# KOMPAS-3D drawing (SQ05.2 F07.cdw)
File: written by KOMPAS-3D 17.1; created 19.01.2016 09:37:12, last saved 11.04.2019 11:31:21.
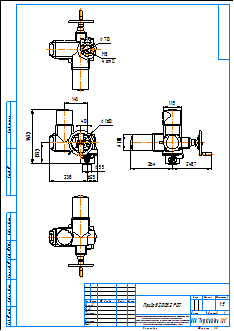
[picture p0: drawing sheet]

Sheet 1: A3, portrait

Title block, sheet 1: name: Привод SQ05.2 F07; material: Внимание! Данный продукт является объектом авторского права ООО «Торговый Дом АДЛ». / Запрещается изменение, копирование, распространение / (в том числе путем копирования на другие сайты и ресурсы в Интернете) / или любое иное использование информации и объектов без предварительного / согласия правообладателя (ООО «Торговый Дом АДЛ»).; scale: 1:5; sheets: 1; organisation: ООО "Торговый дом АДЛ"; sheet format: A3; stored path: \\adlc.lan\data\АДЛ_ПКД\3D-модели\Поставщики\Сервоприводы AUMA\Электроприводы серии SQ\KOMPAS 2D\SQ05.2 F07.cdw

Views: Вид 1, Проекционный вид 2, Проекционный вид 3, Проекционный вид 4
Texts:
  Klimkovich
Dimensions and other numbers on the sheet: 343,5; 160; 133,5; 62,5; 238; 40; 143; 55; 248,7; 264; 115; 101; 70; 8; 4 отв.; 1:5; 1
